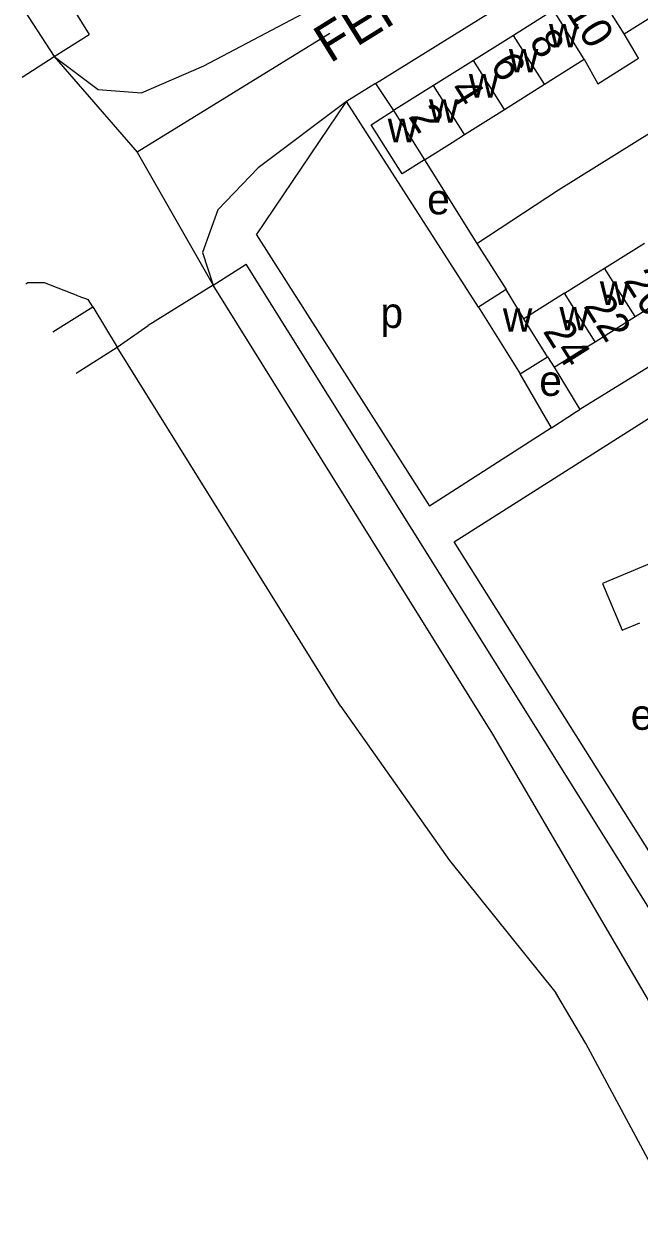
# Model space of a CAD drawing. Extents: x 159675 to 162108, y 386471 to 388472.
# Drawn here: x 160373.3 to 160453.9, y 386719 to 386875.3 of the extents above; entities that cross this region are included whole.
import ezdxf

# ---------------------------------------------------------------- set-up
doc = ezdxf.new("R2010")
doc.units = 0
for name, color, linetype in [('BLT_Basislijn', 7, 'Continuous'), ('BLT_Bebouwing', 7, 'Continuous'), ('BLT_Centroide', 7, 'Continuous'), ('BLT_Huisnummer', 7, 'Continuous'), ('BLT_Huisnummer_ tussenligend', 7, 'Continuous'), ('BLT_Onderverdeling_panden', 7, 'Continuous'), ('BLT_Straatnaam', 7, 'Continuous'), ('BLT_Vlakafsluiter', 7, 'Continuous')]:
    doc.layers.add(name, color=color, linetype=linetype)

msp = doc.modelspace()

# ---------------------------------------------------------------- linework, layer by layer
at = {"layer": 'BLT_Basislijn'}
for p, q in [((160338.01, 386944.36), (160381.82, 386873.92)), ((160335.47, 386935.73), (160377.24, 386871.02)), ((160419.31, 386867.46), (160482.4, 386906.73)), ((160377.24, 386871.02), (160381.82, 386873.92)), ((160413.35, 386874.02), (160388.13, 386858.49)), ((160419.31, 386867.46), (160421.68, 386863.93)), ((160403.75, 386847.65), (160415.51, 386865.11)), ((160425.75, 386857.48), (160432.59, 386846.5)), ((160403.75, 386847.65), (160426.4, 386812.07)), ((160432.59, 386846.5), (160436.45, 386840.46)), ((160476.7, 386843.66), (160446.1, 386824.74)), ((160377.05, 386834.92), (160382.29, 386838.21)), ((160380.35, 386839.66), (160381.7, 386839.15)), ((160382.29, 386838.21), (160385.47, 386832.91)), ((160442.73, 386830.27), (160446.1, 386824.74)), ((160429.63, 386807.4), (160460.2, 386826.83)), ((160442.38, 386822.34), (160426.4, 386812.07)), ((160477.76, 386730.85), (160429.63, 386807.4))]:
    msp.add_line(p, q, dxfattribs=at)
for points in [[(160377.24, 386871.02), (160383.02, 386866.69), (160388.69, 386866.26), (160396.85, 386869.81), (160413.09, 386878.37), (160421.38, 386887.05)], [(160432.59, 386846.5), (160443.32, 386853.54), (160495.39, 386886.04)], [(160419.31, 386867.46), (160418.76, 386867.12), (160415.51, 386865.11)], [(160415.51, 386865.11), (160403.97, 386856.44), (160398.66, 386850.91), (160396.68, 386845.31), (160398.07, 386841.06)], [(160432.8, 386838.17), (160415.51, 386865.11)], [(160398.07, 386841.06), (160402.37, 386843.78)], [(160502.2, 386684.09), (160500, 386687.6), (160402.37, 386843.78)], [(160380.35, 386839.66), (160375.97, 386841.34), (160375.97, 386841.34), (160373.78, 386841.34), (160373.51, 386841.17)], [(160555.29, 386582.71), (160503.52, 386666.51), (160477.52, 386707.61), (160471.13, 386717.59), (160455.58, 386746.48), (160434.69, 386782.15), (160398.07, 386841.06)], [(160382.29, 386838.21), (160381.7, 386839.15)], [(160380.12, 386829.52), (160385.47, 386832.91)], [(160414.77, 386785.79), (160385.47, 386832.91)], [(160442.38, 386822.34), (160438.3, 386829.4)], [(160442.38, 386822.34), (160445.65, 386824.46), (160446.1, 386824.74)], [(160414.77, 386785.79), (160429.02, 386765.6), (160442.95, 386748.27)], [(160548.19, 386575.18), (160495.04, 386661.2), (160469.08, 386702.24), (160462.5, 386712.51), (160446.86, 386741.59), (160442.95, 386748.27)]]:
    msp.add_lwpolyline(points, dxfattribs=at)
at = {"layer": 'BLT_Bebouwing'}
for p, q in [((160451.91, 386873.98), (160457.15, 386877.28)), ((160442.65, 386877.08), (160437.4, 386873.79)), ((160437.4, 386873.79), (160432.16, 386870.5)), ((160432.16, 386870.5), (160426.92, 386867.22)), ((160441.45, 386867.38), (160446.68, 386870.68)), ((160426.92, 386867.22), (160421.68, 386863.93)), ((160436.21, 386864.08), (160441.45, 386867.38)), ((160430.98, 386860.78), (160436.21, 386864.08)), ((160449.34, 386843.27), (160454.58, 386846.55)), ((160453.34, 386836.93), (160458.58, 386840.22)), ((160448.1, 386833.63), (160453.34, 386836.93))]:
    msp.add_line(p, q, dxfattribs=at)
for points in [[(160446.68, 386870.68), (160448.44, 386867.44), (160453.78, 386870.81), (160451.91, 386873.98)], [(160425.75, 386857.48), (160422.84, 386855.65), (160418.77, 386862.08), (160421.68, 386863.93)], [(160425.75, 386857.48), (160429.35, 386859.75), (160430.98, 386860.78)], [(160444.1, 386839.98), (160448.2, 386842.55), (160449.34, 386843.27)], [(160436.45, 386840.46), (160432.8, 386838.17)], [(160438.74, 386836.62), (160436.45, 386840.46)], [(160444.1, 386839.98), (160443.27, 386839.46), (160438.74, 386836.62)], [(160432.8, 386838.17), (160438.3, 386829.4)], [(160442.73, 386830.27), (160446.35, 386832.54), (160448.1, 386833.63)], [(160438.3, 386829.4), (160441.87, 386831.64)], [(160441.87, 386831.64), (160442.73, 386830.27)], [(160464.53, 386805.89), (160463.52, 386808.26), (160463.16, 386808.1), (160463.27, 386807.84), (160461.26, 386806.99), (160461.6, 386806.19), (160456.39, 386803.99), (160456.03, 386804.85), (160449.08, 386801.91), (160451.66, 386795.8), (160453.96, 386796.77)]]:
    msp.add_lwpolyline(points, dxfattribs=at)
at = {"layer": 'BLT_Onderverdeling_panden'}
for p, q in [((160451.91, 386873.98), (160447.89, 386880.36)), ((160446.68, 386870.68), (160442.65, 386877.08)), ((160441.45, 386867.38), (160437.4, 386873.79)), ((160436.21, 386864.08), (160432.16, 386870.5)), ((160430.98, 386860.78), (160426.92, 386867.22)), ((160421.68, 386863.93), (160425.75, 386857.48)), ((160453.34, 386836.93), (160449.34, 386843.27)), ((160448.1, 386833.63), (160444.1, 386839.98)), ((160441.87, 386831.64), (160438.74, 386836.62))]:
    msp.add_line(p, q, dxfattribs=at)
at = {"layer": 'BLT_Vlakafsluiter'}
for p, q in [((160373.03, 386868.31), (160377.24, 386871.02)), ((160377.24, 386871.02), (160388.13, 386858.49)), ((160388.13, 386858.49), (160398.07, 386841.06)), ((160398.07, 386841.06), (160389.57, 386835.77)), ((160385.47, 386832.91), (160389.57, 386835.77))]:
    msp.add_line(p, q, dxfattribs=at)

# ---------------------------------------------------------------- texts
at = {"layer": 'BLT_Centroide'}
for s, p in [('w', (160442.05, 386872.22)), ('w', (160436.8, 386868.94)), ('w', (160431.56, 386865.64)), ('w', (160426.33, 386862.34)), ('w', (160420.93, 386859.78)), ('e', (160426.09, 386850.32)), ('w', (160448.72, 386838.45)), ('p', (160419.98, 386835.43)), ('w', (160436.01, 386834.95)), ('w', (160443.42, 386835.12)), ('e', (160440.78, 386826.52)), ('e', (160452.75, 386782.74))]:
    msp.add_text(s, height=4, dxfattribs=at).set_placement(p)
at = {"layer": 'BLT_Huisnummer'}
for s, rotation, p in [('10', 302.2405, (160444.23, 386876.81)), ('6', 302.2405, (160434.27, 386869.94)), ('2', 302.2405, (160423.55, 386863.18)), ('24', 302.2323, (160441.18, 386835))]:
    msp.add_text(s, height=4, rotation=rotation, dxfattribs=at).set_placement(p)
at = {"layer": 'BLT_Huisnummer_ tussenligend'}
for s, rotation, p in [('8', 302.2378, (160439.36, 386872.99)), ('4', 302.2378, (160428.84, 386866.65)), ('20', 302.2346, (160451.74, 386841.62)), ('22', 302.2346, (160446.49, 386838.32))]:
    msp.add_text(s, height=4, rotation=rotation, dxfattribs=at).set_placement(p)
at = {"layer": 'BLT_Straatnaam'}
msp.add_text('FERDINAND HUYCKSTRAAT', height=5, rotation=31.8297, dxfattribs=at).set_placement((160413.37, 386870.07))

doc.saveas('drawing.dxf')
